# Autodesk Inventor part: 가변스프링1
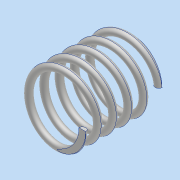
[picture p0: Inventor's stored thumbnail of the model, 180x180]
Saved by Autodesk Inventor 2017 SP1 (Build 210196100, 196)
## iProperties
Part Number: 가변스프링1
Material: 알루미늄 6061
Document SubType Name: Modeling
Designer: MRC
Density: 2.7 g/cm^3
Appearance: 알루미늄 - 평지
Mass: 2.35518 g
Surface Area: 17.713 cm^2
Volume: 0.872289 cm^3
Author: MRC
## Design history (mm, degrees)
sketch "스케치1"
  geometry: L1 (0, 0)-(0, 22.5); L2 (0, 22.5)-(9, 22.5); L3 (0, 0)-(9, 0); C1 r 1 at (9, 0)
  constraints: 6 end point, 1 centre point, 1 coincident, 1 horizontal, 1 perpendicular, 1 vertical
  dimensions: "d0" = 22.5 distance of L1.start L1.end (derived); "d1" = 9 distance of L1.end L2.end; "d2" = 9 distance of L1.start L3.end; "d3" = 2 diameter of C1
feature "코일1" pitch "d4" = 10; turns "d6" = 5; dims "d5" = 22.5 (= d0), "d7" = 0, angle "d8" = 90 deg, angle "d9" = 90 deg, "d10" = 0, "d11" = 0
sketch "스케치2"
  geometry: L1 (22.5, 15)-(0, 15); L2 (0, 15)-(0, -15); L3 (0, -15)-(22.5, -15); L4 (22.5, -15)-(22.5, 15); 2 further points
  constraints: 8 end point, 2 midpoint, 2 parallel, 1 coincident, 1 horizontal, 1 perpendicular
  dimensions: "d12" = 30 distance of L3.end L1.start; "d13" = 22.5 distance of L1.start L1.end (= d0)
extrude "돌출2" sketch "스케치2" stored distance "d16" = 0; taper "d17" = 0 deg
node "솔리드1"
